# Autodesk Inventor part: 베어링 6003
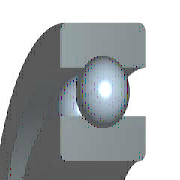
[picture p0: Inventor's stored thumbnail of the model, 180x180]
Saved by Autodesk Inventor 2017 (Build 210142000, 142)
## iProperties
Created: 2012-02
Part Number: 베어링 6003
Material: 강철, 연강
Description: 깊은 그루브 볼 베어링
Document SubType Name: Modeling
Standard: KS B 2023
Designer: mduedu
Standards Organization: KS
Language: ko-KR
Size Designation: 6003 - 17 x 35 x 10
Categories: <MemberInstance><Categories><Category DisplayName="샤프트 부품" InternalName="7f7aeb1f-a693-4053-b835-cee3144e0d98" Mnemonic="SHFT"><Category DisplayName="베어링" Inter
Density: 1 g/cm^3
Appearance: 밝은 황색
IsCustomPart: 1
Author: mduedu
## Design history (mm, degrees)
sketch "스케치" dims "d0" = 4.68 (= -0.26 x WD + 0.26 x BD)
  geometry: L1 (2.66, 13)-(7.34, 13); L2 (5, 13)-(5, 10.66); L3 (5, 13)-(5, 15.34); L4 (3.261, 11.434)-(0, 11.434); L5 (0, 8.5)-(10, 8.5); L6 (3.261, 14.566)-(0, 14.566); L7 (0, 17.5)-(10, 17.5); L8 (10, 8.5)-(10, 11.434); L9 (6.739, 11.434)-(10, 11.434); L10 (6.739, 14.566)-(10, 14.566); L11 (10, 17.5)-(10, 14.566); L12 (-1.4, 0)-(8.4, 0) reference; L13 (0, -0.3)-(0, 5.3) reference
  constraints: 22 end point, 4 point on line, 2 collinear, 2 perpendicular, 2 symmetric about line, 1 midpoint, 1 parallel, 14 other
  dimensions: "d9" = 17 diameter of L5 L12 (= WD); "d11" = 35 diameter of L7 L12 (= BD); "d12" = 10 distance between parallel lines of L8 L13 (= KB); "d13" = 22.868 diameter of L9 L12 (= 0.326 x BD + 0.674 x WD)
revolve "본체" stored, may be unused: angle "d6" = 90 deg
revolve "볼" stored, may be unused: angle "d7" = 90 deg
pattern_circular "IDS_ARRAYBALL[SIMPL:T]" dims angle "d3" = 360 deg
body "Solid1"
fillet "모깎기1" dims "d1" = 0.3 (= KRS)
other parameters: "WD" = 17 [user parameter; used in 5 equation terms], "BD" = 35 [user parameter; used in 5 equation terms], "KB" = 10 [user parameter; used in 1 equation term], "KRS" = 0.3 [user parameter; used in 1 equation term], "d4" = 0, "d5" = 0, "d8" = 0, "d14" = 0, "d15" = 0, "BBA" = 0 [user parameter], "BC0" = 3250000 [user parameter], "BC" = 6050000 [user parameter], "BR" = 17.5 (= 0.5 x BD) [user parameter], "WR" = 8.5 (= 0.5 x WD) [user parameter]
